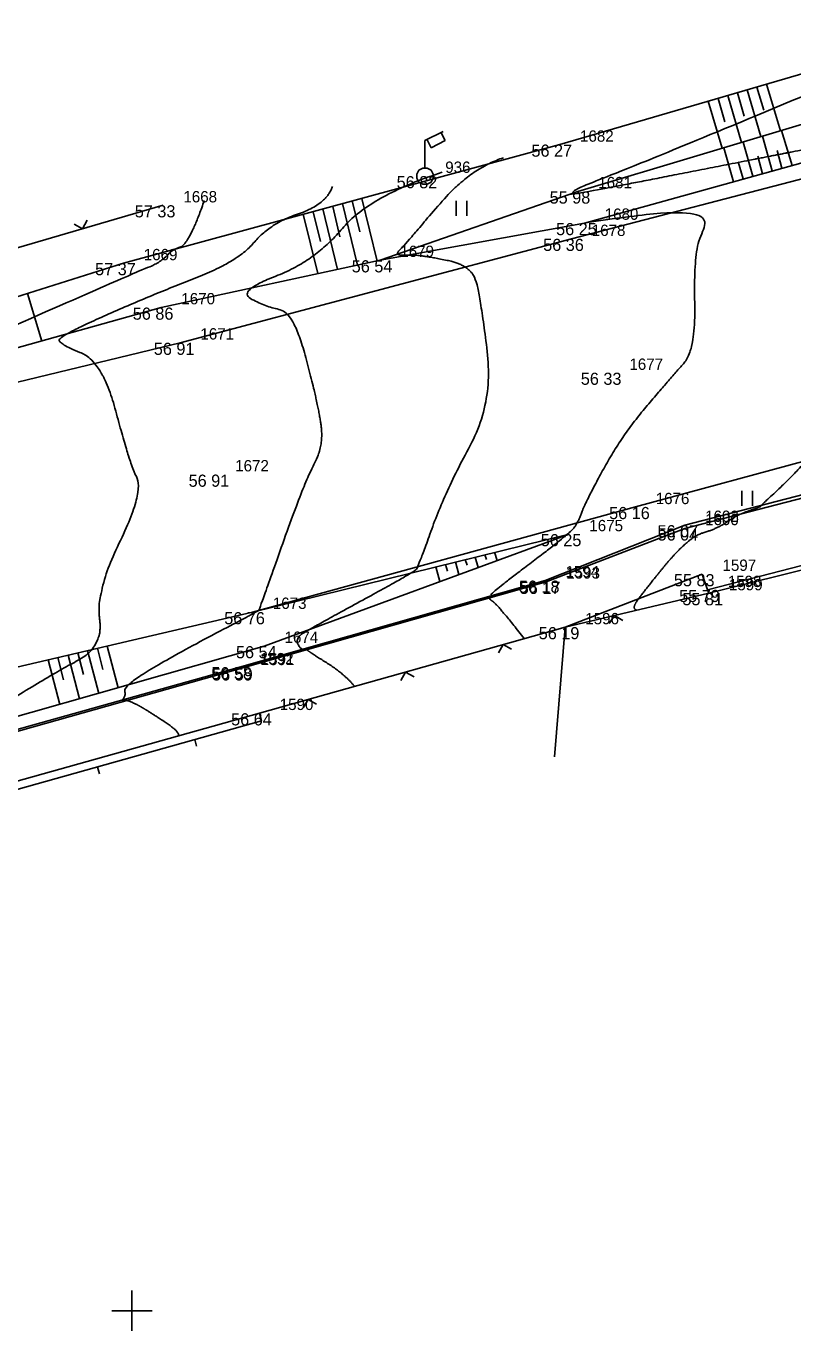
# Model space of a CAD drawing. Extents: x -704017 to -701500, y -1008977 to -1008450.
# Drawn here: x -702702.61 to -702683.67, y -1008800.5 to -1008768.24 of the extents above; entities that cross this region are included whole.
import ezdxf

# ---------------------------------------------------------------- set-up
doc = ezdxf.new("R2010")
doc.units = 0
for name, color, linetype in [('Z_body', 7, 'Continuous'), ('Z_body_cisla', 7, 'Continuous'), ('Z_body_vysky', 7, 'Continuous'), ('Z_chodnik', 7, 'Continuous'), ('Z_hekt_sit', 7, 'Continuous'), ('Z_komunikace', 7, 'Continuous'), ('Z_obruby', 7, 'Continuous'), ('Z_oploceni', 7, 'Continuous'), ('Z_popis', 7, 'Continuous'), ('Z_site_znaky_VO', 7, 'Continuous'), ('Z_teren_hrany_paty', 7, 'Continuous'), ('Z_vrstevnice_hlavni', 7, 'Continuous'), ('Z_vrstevnice_vedlejsi', 7, 'Continuous'), ('Z_vstupy', 7, 'Continuous')]:
    doc.layers.add(name, color=color, linetype=linetype)

# ---------------------------------------------------------------- blocks, each defined once
blk = doc.blocks.new('POINT_DISPLAY')
blk.add_line((0, 0), (0, 0))
blk = doc.blocks.new('Z212')
for p, q in [((-0.17, 0.17), (0, 0)), ((0, 0), (0.17, 0.17))]:
    blk.add_line(p, q)
blk = doc.blocks.new('Z210')
blk.add_line((0, 0), (0, 0.17))
blk = doc.blocks.new('Z306')
for p, q in [((-0.13, 0.17), (-0.13, -0.2)), ((0.13, 0.17), (0.13, -0.2))]:
    blk.add_line(p, q)
blk = doc.blocks.new('Z13')
for p, q in [((0, 0.88), (0.45, 1.1)), ((0.4, 1.07), (0.5, 0.88)), ((0, 0.2), (0, 0.88)), ((0.15, 0.7), (0.05, 0.9)), ((0.5, 0.88), (0.15, 0.7)), ((-0.2, 0.05), (-0.15, 0.15)), ((-0.2, -0.05), (-0.2, 0.05)), ((-0.15, 0.15), (-0.05, 0.2)), ((-0.05, 0.2), (0.05, 0.2)), ((0.05, 0.2), (0.15, 0.15)), ((0.15, 0.15), (0.2, 0.05)), ((0.2, 0.05), (0.2, -0.05)), ((-0.15, -0.15), (-0.2, -0.05)), ((-0.05, -0.2), (-0.15, -0.15)), ((0.05, -0.2), (-0.05, -0.2)), ((0.15, -0.15), (0.05, -0.2)), ((0.2, -0.05), (0.15, -0.15))]:
    blk.add_line(p, q)

msp = doc.modelspace()

# ---------------------------------------------------------------- linework, layer by layer
at = {"layer": 'Z_chodnik'}
for p, q in [((-702686.34, -1008780.66), (-702681.52, -1008779.41)), ((-702689.77, -1008781.98), (-702686.34, -1008780.66)), ((-702685.78, -1008782.18), (-702681.68, -1008781.12)), ((-702697.32, -1008784.12), (-702689.77, -1008781.98)), ((-702689.3, -1008783.1), (-702685.91, -1008781.79)), ((-702685.91, -1008781.79), (-702685.78, -1008782.18)), ((-702685.78, -1008782.18), (-702685.75, -1008782.26)), ((-702707.04, -1008786.87), (-702697.32, -1008784.12))]:
    msp.add_line(p, q, dxfattribs=at)
at = {"layer": 'Z_hekt_sit'}
for p, q in [((-702700, -1008799.5), (-702700, -1008800.5)), ((-702700.5, -1008800), (-702699.5, -1008800))]:
    msp.add_line(p, q, dxfattribs=at)
at = {"layer": 'Z_komunikace'}
for p, q in [((-702689.14, -1008773.5), (-702679.77, -1008771.06)), ((-702698.81, -1008776.07), (-702689.14, -1008773.5)), ((-702707.31, -1008778.13), (-702698.81, -1008776.07)), ((-702687.56, -1008780.13), (-702678.53, -1008777.67)), ((-702697.02, -1008782.73), (-702687.56, -1008780.13)), ((-702706.06, -1008784.84), (-702697.02, -1008782.73))]:
    msp.add_line(p, q, dxfattribs=at)
at = {"layer": 'Z_obruby'}
for p, q in [((-702686.34, -1008780.58), (-702681.52, -1008779.33)), ((-702689.79, -1008781.95), (-702686.34, -1008780.58)), ((-702686.34, -1008780.58), (-702686.34, -1008780.58)), ((-702697.34, -1008784.09), (-702689.79, -1008781.95)), ((-702707.05, -1008786.81), (-702697.34, -1008784.09))]:
    msp.add_line(p, q, dxfattribs=at)
at = {"layer": 'Z_oploceni'}
for p, q in [((-702707.22, -1008775.01), (-702699.23, -1008772.67)), ((-702689.3, -1008783.1), (-702685.75, -1008782.26)), ((-702696.85, -1008785.23), (-702689.3, -1008783.1)), ((-702689.3, -1008783.1), (-702689.56, -1008786.31)), ((-702706.91, -1008788.05), (-702696.85, -1008785.23)), ((-702706.87, -1008788.25), (-702696.8, -1008785.42)), ((-702696.8, -1008785.42), (-702696.85, -1008785.23))]:
    msp.add_line(p, q, dxfattribs=at)
at = {"layer": 'Z_teren_hrany_paty'}
for p, q in [((-702689.43, -1008771.17), (-702680.63, -1008768.6)), ((-702688.98, -1008772.33), (-702680.22, -1008769.7)), ((-702684.32, -1008769.68), (-702683.98, -1008770.83)), ((-702685.52, -1008770.03), (-702685.35, -1008770.61)), ((-702685.28, -1008769.96), (-702684.94, -1008771.12)), ((-702685.04, -1008769.89), (-702684.87, -1008770.47)), ((-702684.8, -1008769.82), (-702684.46, -1008770.97)), ((-702684.56, -1008769.75), (-702684.39, -1008770.32)), ((-702685.76, -1008770.1), (-702685.42, -1008771.26)), ((-702688.82, -1008773.11), (-702679.92, -1008770.64)), ((-702684.18, -1008771.82), (-702684.42, -1008770.96)), ((-702683.69, -1008771.69), (-702683.95, -1008770.82)), ((-702700.21, -1008774.1), (-702689.43, -1008771.17)), ((-702685.14, -1008772.09), (-702685.38, -1008771.25)), ((-702684.66, -1008771.95), (-702684.9, -1008771.11)), ((-702683.94, -1008771.75), (-702684.06, -1008771.32)), ((-702684.9, -1008772.02), (-702685.02, -1008771.6)), ((-702684.42, -1008771.89), (-702684.54, -1008771.46)), ((-702694.8, -1008772.63), (-702694.43, -1008774.15)), ((-702694.56, -1008772.56), (-702694.37, -1008773.33)), ((-702694.32, -1008772.5), (-702693.94, -1008774.05)), ((-702693.87, -1008774.03), (-702688.98, -1008772.33)), ((-702695.77, -1008772.89), (-702695.41, -1008774.36)), ((-702695.52, -1008772.83), (-702695.34, -1008773.57)), ((-702695.28, -1008772.76), (-702694.92, -1008774.26)), ((-702695.04, -1008772.7), (-702694.86, -1008773.45)), ((-702693.87, -1008774.03), (-702688.82, -1008773.11)), ((-702707.86, -1008776.53), (-702700.21, -1008774.1)), ((-702699.28, -1008775.2), (-702693.87, -1008774.03)), ((-702702.58, -1008774.85), (-702702.23, -1008776.03)), ((-702707.61, -1008777.53), (-702699.28, -1008775.2)), ((-702689.2, -1008780.8), (-702697.02, -1008782.73)), ((-702696.73, -1008783.57), (-702689.2, -1008780.8)), ((-702691.28, -1008781.31), (-702691.24, -1008781.43)), ((-702691.04, -1008781.25), (-702690.98, -1008781.45)), ((-702692.49, -1008781.61), (-702692.39, -1008781.97)), ((-702692.25, -1008781.55), (-702692.2, -1008781.72)), ((-702692.01, -1008781.49), (-702691.92, -1008781.8)), ((-702691.77, -1008781.43), (-702691.72, -1008781.57)), ((-702691.52, -1008781.37), (-702691.45, -1008781.63)), ((-702705.96, -1008786.2), (-702696.73, -1008783.57)), ((-702700.61, -1008783.57), (-702700.34, -1008784.6)), ((-702702.07, -1008783.91), (-702701.78, -1008785.01)), ((-702701.83, -1008783.85), (-702701.69, -1008784.4)), ((-702701.58, -1008783.79), (-702701.3, -1008784.87)), ((-702701.34, -1008783.74), (-702701.2, -1008784.27)), ((-702701.1, -1008783.68), (-702700.82, -1008784.74)), ((-702700.85, -1008783.62), (-702700.72, -1008784.15))]:
    msp.add_line(p, q, dxfattribs=at)
at = {"layer": 'Z_vrstevnice_hlavni'}
for points in [[(-702687.525, -1008782.68), (-702687.628, -1008782.663), (-702687.511, -1008782.409), (-702686.258, -1008780.875), (-702685.545, -1008780.672), (-702685.055, -1008780.327), (-702684.466, -1008780.125), (-702684.466, -1008780.094), (-702683.981, -1008779.656), (-702683.311, -1008778.972), (-702681.946, -1008777.366), (-702679.32, -1008774.4), (-702675.533, -1008771.027), (-702674.634, -1008769.634), (-702677.342, -1008770.268), (-702679.35, -1008770.501), (-702679.926, -1008770.622), (-702682.94, -1008771.203), (-702688.968, -1008772.388), (-702689.155, -1008772.391), (-702689.011, -1008772.25), (-702687.588, -1008771.708), (-702680.562, -1008768.783), (-702679.278, -1008768.241)], [(-702703.435, -1008787.076), (-702703.131, -1008786.839), (-702703.415, -1008786.651), (-702704.436, -1008786.133), (-702704.487, -1008786.138), (-702704.495, -1008786.094), (-702704.302, -1008785.794), (-702704.312, -1008785.73), (-702702.029, -1008784.291), (-702700.697, -1008783.588), (-702700.9, -1008782.23), (-702699.704, -1008779.76), (-702700.056, -1008779.06), (-702700.723, -1008776.534), (-702701.778, -1008776.112), (-702701.815, -1008775.909), (-702699.535, -1008774.898), (-702697.384, -1008774.069), (-702696.584, -1008773.114), (-702695.198, -1008772.654), (-702695.044, -1008772.204)]]:
    msp.add_open_spline(points, degree=2, dxfattribs=at)
at = {"layer": 'Z_vrstevnice_vedlejsi'}
for points in [[(-702694.501, -1008784.567), (-702694.741, -1008784.262), (-702695.702, -1008783.661), (-702695.667, -1008783.644), (-702695.83, -1008783.662), (-702695.959, -1008783.39), (-702695.691, -1008783.188), (-702693.033, -1008781.746), (-702692.921, -1008781.603), (-702692.27, -1008779.767), (-702691.065, -1008777.549), (-702691.383, -1008774.984), (-702691.601, -1008774.154), (-702692.819, -1008773.912), (-702693.173, -1008773.903), (-702693.521, -1008773.909), (-702693.212, -1008773.606), (-702691.684, -1008771.783), (-702690.823, -1008771.496)], [(-702698.862, -1008785.794), (-702698.769, -1008785.721), (-702699.698, -1008785.108), (-702700.097, -1008784.906), (-702700.233, -1008784.919), (-702700.236, -1008784.901), (-702700.158, -1008784.78), (-702700.191, -1008784.556), (-702699.149, -1008783.899), (-702697.007, -1008782.768), (-702696.867, -1008782.692), (-702696.862, -1008782.687), (-702695.733, -1008779.501), (-702695.263, -1008778.635), (-702695.387, -1008777.634), (-702695.997, -1008775.322), (-702696.674, -1008775.188), (-702697.42, -1008774.798), (-702695.474, -1008774.048), (-702694.134, -1008772.449), (-702692.336, -1008771.851)], [(-702714.122, -1008788.788), (-702714.177, -1008788.706), (-702716.133, -1008787.75), (-702716.119, -1008787.736), (-702715.106, -1008787.603), (-702717.626, -1008787.765), (-702717.591, -1008787.692), (-702714.115, -1008787.211), (-702707.284, -1008786.126), (-702706.677, -1008785.89), (-702706.02, -1008785.384), (-702704.908, -1008784.683), (-702704.528, -1008784.482), (-702704.942, -1008781.709), (-702704.576, -1008780.954), (-702705.906, -1008778.31), (-702706.035, -1008777.821), (-702706.239, -1008777.739), (-702706.342, -1008777.175), (-702699.991, -1008774.359), (-702699.293, -1008774.09), (-702699.034, -1008773.78), (-702698.585, -1008773.631), (-702698.215, -1008772.557)], [(-702690.307, -1008783.384), (-702690.975, -1008782.533), (-702691.208, -1008782.388), (-702691.076, -1008782.32), (-702691.111, -1008782.325), (-702691.139, -1008782.265), (-702689.2, -1008780.8), (-702688.979, -1008780.52), (-702688.807, -1008780.034), (-702687.904, -1008778.372), (-702686.692, -1008776.945), (-702686.055, -1008776.226), (-702686.139, -1008773.775), (-702685.586, -1008772.574), (-702688.82, -1008773.11)]]:
    msp.add_open_spline(points, degree=2, dxfattribs=at)
at = {"layer": 'Z_vstupy'}
msp.add_line((-702685.75, -1008782.26), (-702681.62, -1008781.23), dxfattribs=at)

# ---------------------------------------------------------------- block references
at = {"layer": 'Z_body'}
for p in [(-702689.43, -1008771.17), (-702692.76, -1008771.95), (-702688.98, -1008772.33), (-702699.23, -1008772.67), (-702688.82, -1008773.11), (-702689.14, -1008773.5), (-702700.21, -1008774.1), (-702693.87, -1008774.03), (-702699.28, -1008775.2), (-702698.81, -1008776.07), (-702688.21, -1008776.81), (-702697.95, -1008779.33), (-702687.56, -1008780.13), (-702686.34, -1008780.58), (-702686.34, -1008780.66), (-702689.2, -1008780.8), (-702689.79, -1008781.95), (-702689.77, -1008781.98), (-702685.91, -1008781.79), (-702685.78, -1008782.18), (-702685.75, -1008782.26), (-702697.02, -1008782.73), (-702689.3, -1008783.1), (-702696.73, -1008783.57), (-702697.34, -1008784.09), (-702697.32, -1008784.12), (-702696.85, -1008785.23)]:
    msp.add_blockref('POINT_DISPLAY', p, dxfattribs=at)
at = {"layer": 'Z_oploceni'}
for name, p, rotation in [('Z212', (-702701.22, -1008773.25), 16.3), ('Z212', (-702688.08, -1008782.81), -166.70000000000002), ('Z212', (-702690.83, -1008783.53), -164.20000000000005), ('Z212', (-702693.24, -1008784.21), -164.20000000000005), ('Z212', (-702695.65, -1008784.89), -164.20000000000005), ('Z210', (-702698.45, -1008785.88), -164.30000000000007), ('Z210', (-702700.85, -1008786.56), -164.30000000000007)]:
    msp.add_blockref(name, p, dxfattribs=dict(at, rotation=rotation))
at = {"layer": 'Z_popis'}
for p in [(-702691.86, -1008772.73), (-702684.8, -1008779.9)]:
    msp.add_blockref('Z306', p, dxfattribs=at)
at = {"layer": 'Z_site_znaky_VO'}
msp.add_blockref('Z13', (-702692.76, -1008771.95), dxfattribs=at)

# ---------------------------------------------------------------- texts
at = {"layer": 'Z_body_cisla'}
for s, p in [('1682', (-702688.93, -1008771.1)), ('936', (-702692.26, -1008771.87)), ('1681', (-702688.48, -1008772.25)), ('1668', (-702698.73, -1008772.6)), ('1680', (-702688.32, -1008773.03)), ('1678', (-702688.64, -1008773.43)), ('1669', (-702699.71, -1008774.03)), ('1679', (-702693.37, -1008773.95)), ('1670', (-702698.78, -1008775.12)), ('1671', (-702698.31, -1008775.99)), ('1677', (-702687.71, -1008776.74)), ('1672', (-702697.45, -1008779.25)), ('1676', (-702687.06, -1008780.06)), ('1602', (-702685.84, -1008780.5)), ('1600', (-702685.84, -1008780.58)), ('1675', (-702688.7, -1008780.73)), ('1594', (-702689.29, -1008781.87)), ('1593', (-702689.27, -1008781.9)), ('1597', (-702685.41, -1008781.71)), ('1598', (-702685.28, -1008782.11)), ('1599', (-702685.25, -1008782.19)), ('1673', (-702696.52, -1008782.65)), ('1596', (-702688.8, -1008783.03)), ('1674', (-702696.23, -1008783.49)), ('1592', (-702696.84, -1008784.02)), ('1591', (-702696.82, -1008784.04)), ('1590', (-702696.35, -1008785.15))]:
    msp.add_text(s, height=0.28, dxfattribs=at).set_placement(p)
at = {"layer": 'Z_body_vysky'}
for s, p in [('56 27', (-702690.13, -1008771.47)), ('56 82', (-702693.46, -1008772.25)), ('55 98', (-702689.68, -1008772.63)), ('57 33', (-702699.93, -1008772.97)), ('56 25', (-702689.52, -1008773.41)), ('56 36', (-702689.84, -1008773.8)), ('57 37', (-702700.91, -1008774.4)), ('56 54', (-702694.57, -1008774.33)), ('56 86', (-702699.98, -1008775.5)), ('56 91', (-702699.46, -1008776.37)), ('56 33', (-702688.91, -1008777.11)), ('56 91', (-702698.6, -1008779.63)), ('56 16', (-702688.21, -1008780.43)), ('56 07', (-702687.015, -1008780.88)), ('56 04', (-702687.015, -1008780.96)), ('56 25', (-702689.9, -1008781.1)), ('56 18', (-702690.44, -1008782.25)), ('56 17', (-702690.42, -1008782.28)), ('55 83', (-702686.61, -1008782.09)), ('55 79', (-702686.48, -1008782.48)), ('55 81', (-702686.4, -1008782.56)), ('56 76', (-702697.72, -1008783.03)), ('56 19', (-702689.95, -1008783.4)), ('56 54', (-702697.43, -1008783.87)), ('56 58', (-702698.04, -1008784.39)), ('56 59', (-702698.02, -1008784.42)), ('56 64', (-702697.55, -1008785.53))]:
    msp.add_text(s, height=0.3, dxfattribs=at).set_placement(p)

doc.saveas('drawing.dxf')
